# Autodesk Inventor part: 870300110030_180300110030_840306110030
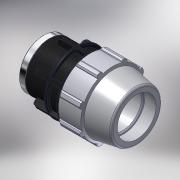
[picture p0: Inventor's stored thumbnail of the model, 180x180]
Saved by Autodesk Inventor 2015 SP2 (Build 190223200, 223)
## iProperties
Created: 2017-02
Part Number: 870300110030_180300110030_840306110030
Material: PVC-Piping
Description: PLASSON FEMALE ADAPTOR 110-3"
Document SubType Name: Modeling
Designer: KIM
Mass: 92.6774 g
Surface Area: 199.44 cm^2
Volume: 66.1981 cm^3
Density: 1.4 g/cm^3
Appearance: PTFE
Author: KIM
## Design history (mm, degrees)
derived "87030.ipt"
feature "Solid1::87030.ipt"
tag "TaggingFeature1"
body "Solid1"
other parameters: "d4" = 37.57143, "d5" = 65.75, "d7" = 181, "d9" = 37.57143, "d11" = 7.51429, "d12" = 144.8, "d13" = 120 deg, "d14" = 143, "d15" = 8 deg, "d16" = 162.9, "d18" = 5.5, "d19" = 35 deg, "d20" = 17.5 deg, "d21" = 168.33, "d23" = 0, "d25" = 360 deg, "d27" = 3.62, "d34" = 9.05, "d35" = 78.9, "d36" = 0, "d42" = 65.75, "d43" = 5.43, "d46" = 3.3, "d49" = 215, "d51" = 263, "d53" = 2.2, "d55" = 360 deg, "d61" = 42, "d62" = 77, "d63" = 84.926, "d64" = 87.66667, "d65" = 9.05, "d69" = 130.32, "d70" = 4.525, "d71" = 12.6, "d72" = 0.5, "d73" = 1, "E_" = 181, "H_" = 263, "l_" = 215, "l_2" = 42, "Rp_Rc_" = 84.926
